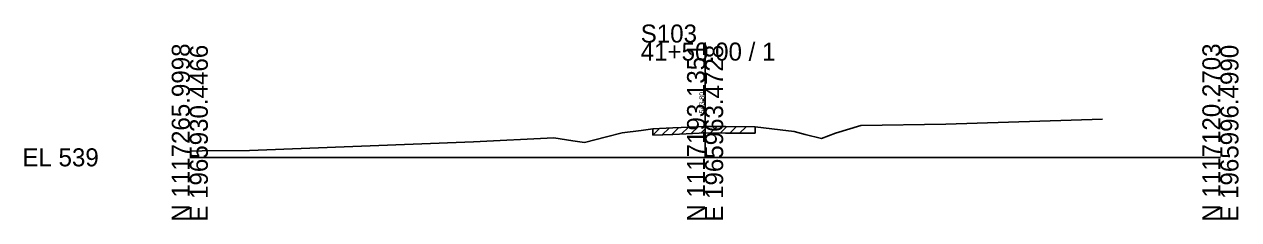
# Model space of a CAD drawing. Extents: x -26 to 163, y -10 to 45020.
# Drawn here: x -25.7 to 162.8, y 1490.3 to 1520.7 of the extents above; entities that cross this region are included whole.
import ezdxf

# ---------------------------------------------------------------- set-up
doc = ezdxf.new("R2010")
doc.units = 0
for name, color, linetype in [('RD_GPK_XS_Cell', 7, 'Continuous'), ('RD_XS_ExGround', 7, 'Continuous'), ('RD_XS_ExPaveRet', 7, 'Continuous'), ('RD_XS_TX_Elev_EX', 7, 'Continuous')]:
    doc.layers.add(name, color=color, linetype=linetype)

msp = doc.modelspace()

# ---------------------------------------------------------------- linework, layer by layer
at = {"layer": 'RD_GPK_XS_Cell'}
for p, q in [((80, 1500), (80, 1517.83)), ((0, 1500), (80, 1500)), ((80, 1500), (160, 1500))]:
    msp.add_line(p, q, dxfattribs=at)
at = {"layer": 'RD_XS_ExGround'}
for p, q in [((71.86, 1504.44), (74.98, 1504.57)), ((74.98, 1504.57), (80.1, 1504.8)), ((80.1, 1504.8), (83.16, 1504.78)), ((83.16, 1504.78), (87.79, 1504.75)), ((87.79, 1504.75), (91.65, 1504.29)), ((100.24, 1503.75), (104.2, 1504.93)), ((104.2, 1504.93), (117.36, 1505.15)), ((117.36, 1505.15), (141.68, 1505.94)), ((44.03, 1502.43), (56.54, 1503.01)), ((56.54, 1503.01), (59.46, 1502.54)), ((61.27, 1502.31), (64.67, 1503.19)), ((64.67, 1503.19), (67.11, 1503.79)), ((67.11, 1503.79), (70.08, 1504.19)), ((70.08, 1504.19), (71.86, 1504.44)), ((91.65, 1504.29), (93.84, 1504.03)), ((93.84, 1504.03), (95.51, 1503.53)), ((95.51, 1503.53), (98.09, 1502.95)), ((98.09, 1502.95), (100.24, 1503.75)), ((0, 1500.97), (1.93, 1501.02)), ((1.93, 1501.02), (9.26, 1501.06)), ((9.26, 1501.06), (44.03, 1502.43)), ((59.46, 1502.54), (61.27, 1502.31))]:
    msp.add_line(p, q, dxfattribs=at)
at = {"layer": 'RD_XS_ExPaveRet'}
for p, q in [((73.36, 1503.5), (74.4, 1504.54)), ((74.86, 1503.56), (75.9, 1504.61)), ((76.36, 1503.63), (77.41, 1504.68)), ((77.86, 1503.7), (78.91, 1504.75)), ((79.36, 1503.77), (80.39, 1504.8)), ((80.86, 1503.79), (81.85, 1504.79)), ((82.36, 1503.78), (83.35, 1504.78)), ((83.86, 1503.78), (84.85, 1504.77)), ((85.36, 1503.77), (86.35, 1504.76)), ((87.79, 1504.75), (87.79, 1503.75)), ((71.86, 1503.44), (72.9, 1504.48)), ((71.86, 1503.44), (71.86, 1504.44)), ((71.86, 1503.44), (74.98, 1503.57)), ((74.98, 1503.57), (80.1, 1503.8)), ((80.1, 1503.8), (83.16, 1503.78)), ((83.16, 1503.78), (87.79, 1503.75))]:
    msp.add_line(p, q, dxfattribs=at)

# ---------------------------------------------------------------- texts
at = {"layer": 'RD_GPK_XS_Cell'}
for s, p in [('S103', (70, 1517.83)), ('41+50.00 / 1', (70, 1515.03)), ('EL 539', (-26, 1498.6))]:
    msp.add_text(s, height=2.8, dxfattribs=at).set_placement(p)
for s, p in [('N 1117265.9998', (0, 1490)), ('E 1965930.4466', (2.8, 1490)), ('N 1117193.1351', (80, 1490)), ('E 1965963.4728', (82.8, 1490)), ('N 1117120.2703', (160, 1490)), ('E 1965996.4990', (162.8, 1490))]:
    msp.add_text(s, height=2.8, rotation=90, dxfattribs=at).set_placement(p)
at = {"layer": 'RD_XS_TX_Elev_EX'}
msp.add_text('543.80', height=0.8, rotation=90, dxfattribs=at).set_placement((79.9, 1506.8))

doc.saveas('drawing.dxf')
